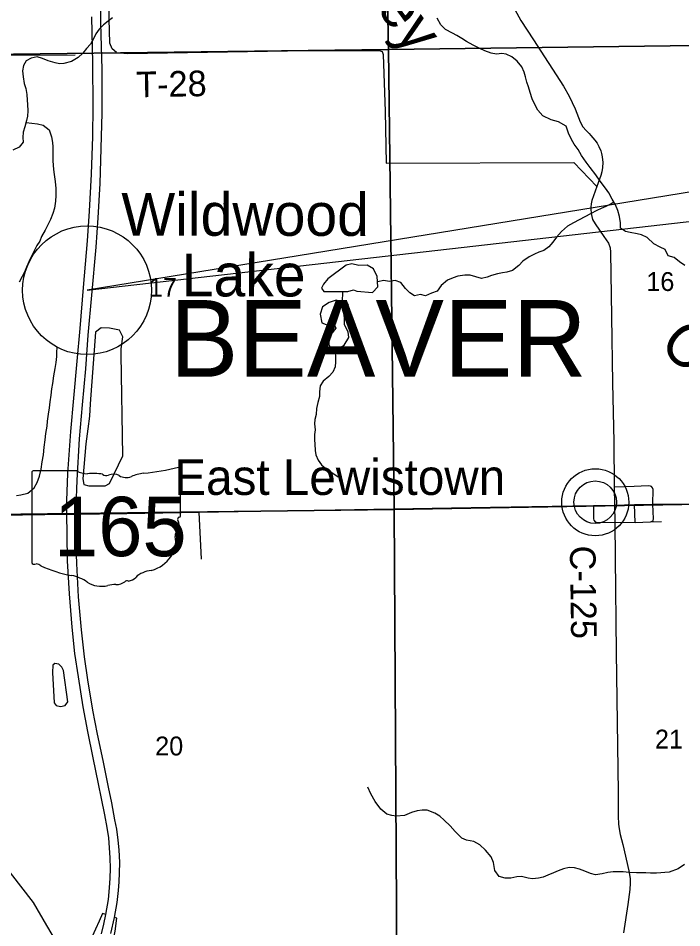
# Model space of a CAD drawing. Extents: x 0 to 36.9, y 0 to 22.
# Drawn here: x 5.386 to 6.858, y 16.582 to 18.601 of the extents above; entities that cross this region are included whole.
import ezdxf

# ---------------------------------------------------------------- set-up
doc = ezdxf.new("R2010")
doc.units = 0
for name, color, linetype in [('GM_X_County_Road', 7, 'Continuous'), ('GM_X_County_Road_Text', 7, 'Continuous'), ('GM_X_Interchange_Ramps', 7, 'Continuous'), ('GM_X_Minor_Lake', 7, 'Continuous'), ('GM_X_Minor_Lake_Text', 7, 'Continuous'), ('GM_X_Minor_River', 7, 'Continuous'), ('GM_X_Minor_River_Text', 7, 'Continuous'), ('GM_X_Section', 7, 'Continuous'), ('GM_X_Section_Text', 7, 'Continuous'), ('GM_X_State_Location', 7, 'Continuous'), ('GM_X_State_Route', 7, 'Continuous'), ('GM_X_State_Shield', 7, 'Continuous'), ('GM_X_Township_Road', 7, 'Continuous'), ('GM_X_Township_Road_Text', 7, 'Continuous'), ('GM_X_Township_Text', 7, 'Continuous'), ('GM_X_Unincorporated', 7, 'Continuous'), ('GM_X_Unincorporated_Location', 7, 'Continuous'), ('GM_X_Unincorporated_Text', 7, 'Continuous'), ('SH_Text', 7, 'Continuous')]:
    doc.layers.add(name, color=color, linetype=linetype)

msp = doc.modelspace()

# ---------------------------------------------------------------- linework, layer by layer
at = {"layer": 'GM_X_County_Road'}
for points in [[(5.6045, 18.5243), (5.5945, 18.533), (5.5895, 18.5452), (5.5877, 18.5992), (5.5866, 18.6737), (5.5863, 18.715), (5.5843, 18.7612), (5.5835, 18.8365), (5.5797, 18.9426), (5.5744, 19.0226), (5.5675, 19.0889), (5.5575, 19.1695), (5.5019, 19.5264)], [(6.3225, 19.0341), (6.3608, 18.9363), (6.4096, 18.8146), (6.4758, 18.6464), (6.4875, 18.6201), (6.5008, 18.5958), (6.5286, 18.5528), (6.5955, 18.45), (6.6081, 18.4277), (6.6215, 18.3998), (6.6322, 18.3709), (6.638, 18.3599), (6.6455, 18.3515), (6.6522, 18.3445)], [(6.6522, 18.3445), (6.6562, 18.3403), (6.6649, 18.3302), (6.67, 18.3232), (6.6739, 18.3157), (6.678, 18.306), (6.6795, 18.3003), (6.6811, 18.2932), (6.6826, 18.2807), (6.6819, 18.2696), (6.6803, 18.2595), (6.678, 18.2515), (6.6692, 18.2272), (6.6617, 18.2064), (6.6586, 18.1962), (6.6571, 18.1886), (6.6562, 18.1816), (6.6558, 18.1758), (6.6565, 18.169)], [(6.6565, 18.169), (6.6567, 18.1671), (6.6582, 18.1604), (6.66, 18.1542), (6.6653, 18.1444), (6.6848, 18.1162), (6.695, 18.1011), (6.699, 18.0909), (6.7, 18.0814), (6.7022, 17.9387), (6.7043, 17.7909), (6.7067, 17.6614), (6.708, 17.5601), (6.7082, 17.5202)], [(6.7082, 17.5202), (6.7089, 17.4821), (6.7097, 17.403), (6.7125, 17.1927), (6.7164, 16.8829), (6.7165, 16.83), (6.7175, 16.8118), (6.7188, 16.8014), (6.7212, 16.7888), (6.7268, 16.7665), (6.7404, 16.7086), (6.7432, 16.6916), (6.7434, 16.6807), (6.7423, 16.6672), (6.7379, 16.634), (6.7285, 16.5707)]]:
    msp.add_lwpolyline(points, dxfattribs=at)
at = {"layer": 'GM_X_Interchange_Ramps'}
for points in [[(5.5806, 16.6115), (5.5732, 16.614), (5.5656, 16.5967), (5.5579, 16.5791), (5.5503, 16.5629), (5.5411, 16.5466), (5.5308, 16.5317), (5.5207, 16.5178), (5.516, 16.5115), (5.5071, 16.5), (5.504, 16.4959)], [(5.5806, 16.3575), (5.584, 16.3603), (5.592, 16.3688), (5.5978, 16.3798), (5.6009, 16.3877), (5.6029, 16.3957), (5.6043, 16.4061), (5.6043, 16.4157), (5.6025, 16.4264), (5.5984, 16.4417), (5.5932, 16.4593), (5.5906, 16.4722), (5.5895, 16.4843), (5.5893, 16.4953), (5.5899, 16.5078), (5.5915, 16.5216), (5.596, 16.5483), (5.6011, 16.5745), (5.605, 16.6036), (5.5996, 16.605)]]:
    msp.add_lwpolyline(points, dxfattribs=at)
at = {"layer": 'GM_X_Minor_Lake'}
for points in [[(6.1721, 17.9919), (6.184, 18.0043), (6.1825, 18.0274), (6.1742, 18.0447), (6.1604, 18.0525), (6.1414, 18.0522), (6.1258, 18.0557), (6.1133, 18.0525), (6.0731, 18.0222), (6.063, 18.0103), (6.059, 18.0015), (6.0637, 17.9939), (6.1169, 17.9941), (6.1294, 17.9981), (6.1374, 17.9948)], [(6.1374, 17.9948), (6.1721, 17.9919)], [(6.1091, 17.956), (6.1189, 17.9652), (6.0913, 17.9746), (6.0758, 17.9698), (6.0608, 17.9601), (6.0557, 17.9441), (6.0595, 17.9248), (6.0732, 17.9197), (6.0869, 17.9206), (6.0908, 17.9124), (6.0822, 17.9023), (6.0744, 17.892), (6.0747, 17.8768), (6.0794, 17.8651), (6.0931, 17.8657), (6.1089, 17.8751), (6.1197, 17.8923), (6.118, 17.9048), (6.114, 17.9112), (6.1101, 17.921)], [(6.1101, 17.921), (6.1091, 17.956)], [(5.6142, 17.8542), (5.6144, 17.8669), (5.6185, 17.8932), (5.6107, 17.9086), (5.5885, 17.9128), (5.5699, 17.9137), (5.5579, 17.9036), (5.5456, 17.745), (5.5446, 17.7173), (5.5408, 17.6891), (5.5361, 17.6564), (5.5293, 17.578), (5.5315, 17.5655), (5.5425, 17.5631), (5.579, 17.5625), (5.5888, 17.568), (5.6186, 17.6294)], [(5.6186, 17.6294), (5.6142, 17.8542)], [(5.4869, 17.1527), (5.4833, 17.1603), (5.4764, 17.167), (5.4676, 17.1683), (5.4627, 17.1645), (5.4626, 17.1485), (5.466, 17.0813), (5.4703, 17.075), (5.4798, 17.0732), (5.4904, 17.0753), (5.496, 17.0837)], [(5.496, 17.0837), (5.4869, 17.1527)]]:
    msp.add_lwpolyline(points, dxfattribs=at)
at = {"layer": 'GM_X_Minor_River'}
for points in [[(5.5956, 18.6016), (5.5855, 18.5942), (5.5754, 18.5857), (5.5657, 18.576), (5.5586, 18.566), (5.5539, 18.5565), (5.5465, 18.543), (5.5379, 18.5334), (5.5294, 18.523), (5.5189, 18.5137), (5.5047, 18.5043), (5.4873, 18.4999), (5.4778, 18.4993), (5.4679, 18.5014), (5.453, 18.5061), (5.44, 18.5112), (5.4285, 18.5148), (5.4149, 18.5119), (5.404, 18.506), (5.3977, 18.4956), (5.3961, 18.4838), (5.3971, 18.4705), (5.3992, 18.4561), (5.4028, 18.4448), (5.4053, 18.4316), (5.4063, 18.4191), (5.4069, 18.4088), (5.4075, 18.3952), (5.407, 18.3834), (5.4049, 18.3739), (5.4009, 18.3594), (5.397, 18.3479), (5.3964, 18.3361), (5.3974, 18.3259), (5.3881, 18.3144), (5.3745, 18.308)], [(6.6767, 18.2387), (6.667, 18.253), (6.6542, 18.2691), (6.6456, 18.2814), (6.6351, 18.296), (6.6276, 18.3092), (6.6194, 18.3208), (6.6135, 18.3317), (6.6065, 18.3453), (6.6012, 18.3611), (6.5844, 18.3707), (6.5683, 18.3749), (6.5496, 18.3841), (6.5383, 18.3968), (6.5309, 18.4103), (6.5257, 18.4216), (6.5213, 18.436), (6.5177, 18.4481), (6.5144, 18.459), (6.5112, 18.4703), (6.508, 18.4809), (6.5028, 18.493), (6.4927, 18.5057), (6.4812, 18.5146), (6.4685, 18.5208), (6.4586, 18.5225), (6.4465, 18.5208), (6.4354, 18.5229), (6.4213, 18.5279), (6.4098, 18.5338), (6.3952, 18.5408), (6.3807, 18.5492), (6.3703, 18.5555), (6.3588, 18.5625), (6.3492, 18.5676), (6.3335, 18.5753), (6.3234, 18.5862), (6.3152, 18.6008)], [(5.4036, 18.3694), (5.4293, 18.366), (5.4419, 18.3631), (5.455, 18.3531), (5.4602, 18.3373), (5.4623, 18.3248), (5.4629, 18.3149), (5.4632, 18.299), (5.463, 18.2842), (5.4636, 18.2747), (5.4645, 18.2649), (5.4659, 18.2535), (5.468, 18.238), (5.4695, 18.2224), (5.4697, 18.2072), (5.4688, 18.1947), (5.4664, 18.1791), (5.4629, 18.1673), (5.4578, 18.1543), (5.4534, 18.1447), (5.446, 18.1305), (5.438, 18.116), (5.434, 18.106), (5.4277, 18.096), (5.4222, 18.0857), (5.4152, 18.0708), (5.4097, 18.06), (5.4046, 18.0478), (5.3999, 18.0374), (5.3947, 18.0275), (5.3885, 18.0152)], [(6.8642, 18.0519), (6.8523, 18.06), (6.8411, 18.0697), (6.8274, 18.0733), (6.8211, 18.0872), (6.8096, 18.0923), (6.7958, 18.1), (6.7811, 18.1142), (6.7685, 18.12), (6.7589, 18.1221), (6.7429, 18.1249), (6.7327, 18.127), (6.7219, 18.1348), (6.7217, 18.1469), (6.7199, 18.1605), (6.7159, 18.1737), (6.7107, 18.1862), (6.7033, 18.1993), (6.6958, 18.2129), (6.6884, 18.2237), (6.6767, 18.2387)], [(6.707, 18.1927), (6.7012, 18.1887), (6.6891, 18.1831), (6.6793, 18.178), (6.6691, 18.1737), (6.6555, 18.1666), (6.6431, 18.16), (6.6175, 18.1466), (6.6043, 18.1388), (6.5912, 18.1272), (6.58, 18.1145), (6.5718, 18.1037), (6.5632, 18.0933), (6.5515, 18.0852), (6.541, 18.0816), (6.5308, 18.0772), (6.5191, 18.0713), (6.5055, 18.0616), (6.4966, 18.0516), (6.4827, 18.0407), (6.4698, 18.0367), (6.4603, 18.0354), (6.4493, 18.0333), (6.4357, 18.0297), (6.4259, 18.0261), (6.4134, 18.0229), (6.4008, 18.0268), (6.3886, 18.0301), (6.3764, 18.0306), (6.3612, 18.0281), (6.3506, 18.0241), (6.3385, 18.019), (6.3243, 18.0077), (6.3154, 17.9951), (6.3025, 17.9907), (6.2893, 17.9847), (6.2786, 17.9876), (6.2649, 17.9847), (6.255, 17.991), (6.2453, 18.0011), (6.2344, 18.0138), (6.2218, 18.0186), (6.2089, 18.0161), (6.1971, 18.0185), (6.1833, 18.0155)], [(6.1051, 17.994), (6.1046, 17.9701)], [(5.3822, 17.5417), (5.3921, 17.543), (5.4076, 17.5467), (5.4218, 17.5583), (5.4284, 17.5699), (5.4335, 17.584), (5.437, 17.6), (5.4397, 17.6164), (5.4421, 17.6316), (5.4441, 17.6483), (5.4457, 17.6647), (5.4477, 17.6788), (5.4501, 17.6955), (5.4514, 17.7066), (5.4534, 17.7222), (5.4558, 17.7363), (5.4574, 17.7496), (5.4595, 17.7637), (5.4611, 17.7781), (5.4628, 17.7903), (5.4655, 17.807), (5.4683, 17.823), (5.4703, 17.8367), (5.4716, 17.8497), (5.4722, 17.8596), (5.4728, 17.8698)], [(6.0885, 17.8655), (6.0896, 17.8508), (6.0901, 17.8379), (6.0888, 17.8273), (6.0837, 17.8154), (6.0751, 17.8054), (6.0623, 17.7953), (6.0556, 17.7849), (6.0543, 17.7712), (6.0541, 17.761), (6.0505, 17.7476), (6.0477, 17.7347), (6.0468, 17.7214), (6.0439, 17.7099), (6.0433, 17.7004), (6.0447, 17.6868), (6.0433, 17.6765), (6.0431, 17.6651), (6.0437, 17.6552), (6.0447, 17.6416), (6.0464, 17.6317), (6.0511, 17.62), (6.0585, 17.6095), (6.0701, 17.5998), (6.082, 17.5924), (6.0954, 17.5828)], [(6.8635, 16.7223), (6.85, 16.7126), (6.83, 16.7054), (6.8019, 16.7033), (6.7883, 16.7035), (6.778, 16.7037), (6.7685, 16.7039), (6.7575, 16.7041), (6.7408, 16.7049), (6.7278, 16.7058), (6.718, 16.706), (6.7058, 16.7062), (6.6937, 16.7044), (6.6812, 16.7015), (6.6664, 16.6998), (6.6554, 16.7026), (6.6428, 16.7073), (6.6309, 16.7117), (6.6195, 16.7149), (6.6081, 16.7154), (6.5956, 16.7125), (6.5839, 16.7085), (6.5733, 16.7038), (6.5605, 16.6986), (6.5503, 16.6946), (6.5401, 16.6922), (6.5265, 16.6908), (6.517, 16.6921), (6.5021, 16.6957), (6.4918, 16.6951), (6.479, 16.6922), (6.4661, 16.692), (6.4531, 16.6959), (6.4434, 16.709), (6.4404, 16.7265), (6.4349, 16.7393), (6.4224, 16.7546), (6.4101, 16.7662), (6.3966, 16.7731), (6.3806, 16.7766), (6.3699, 16.781), (6.3549, 16.7955), (6.344, 16.8079), (6.3309, 16.8209), (6.3212, 16.8295), (6.3104, 16.8365), (6.2932, 16.8427), (6.2822, 16.8432), (6.2709, 16.8415), (6.2584, 16.8379), (6.2426, 16.8315), (6.2244, 16.83), (6.2145, 16.8314), (6.2038, 16.8342), (6.1907, 16.845), (6.1778, 16.8622), (6.1684, 16.8795), (6.1613, 16.8938)]]:
    msp.add_lwpolyline(points, dxfattribs=at)
at = {"layer": 'GM_X_Section'}
for points in [[(7.1591, 19.5574), (7.173, 18.5435), (6.2072, 18.5313), (6.1867, 19.5319)], [(6.1867, 19.5319), (6.2072, 18.5313), (5.197, 18.519), (5.1777, 19.5195)], [(6.2072, 18.5313), (7.173, 18.5435), (7.1983, 17.5272), (6.2201, 17.5106)], [(5.197, 18.519), (6.2072, 18.5313), (6.2201, 17.5106), (5.2141, 17.498)], [(7.1983, 17.5272), (7.2171, 16.5161), (6.226, 16.4996), (6.2201, 17.5106)], [(6.2201, 17.5106), (6.226, 16.4996), (5.2292, 16.4845), (5.2141, 17.498)]]:
    msp.add_lwpolyline(points, close=True, dxfattribs=at)
at = {"layer": 'GM_X_State_Route'}
for points in [[(5.5147, 17.5134), (5.5147, 17.5163), (5.5167, 17.5757), (5.5221, 17.667), (5.5287, 17.7425), (5.5359, 17.8227), (5.5417, 17.8974), (5.5497, 17.9863), (5.559, 18.0927), (5.5636, 18.158), (5.568, 18.2335), (5.5726, 18.3901), (5.5723, 18.4865), (5.5698, 18.5896), (5.5687, 18.6515)], [(5.571, 16.5689), (5.5759, 16.5897), (5.5806, 16.6115), (5.5865, 16.6445), (5.589, 16.6709), (5.5903, 16.692), (5.5908, 16.7139), (5.5902, 16.7369), (5.5887, 16.7596), (5.5869, 16.7816), (5.5836, 16.8043), (5.5781, 16.8328), (5.5711, 16.869), (5.5645, 16.9011), (5.5526, 16.9591), (5.5408, 17.0177), (5.5303, 17.0721), (5.5196, 17.1386), (5.512, 17.1904), (5.5061, 17.249), (5.4997, 17.3228), (5.4959, 17.3965), (5.4946, 17.4549), (5.4944, 17.4998), (5.4944, 17.5107), (5.4943, 17.5306), (5.4962, 17.59), (5.5031, 17.6832), (5.5098, 17.7573), (5.517, 17.8398), (5.5234, 17.9122), (5.5308, 18.003), (5.54, 18.1068), (5.5446, 18.1725), (5.5489, 18.2544), (5.5514, 18.3384), (5.5522, 18.4044), (5.5518, 18.5008), (5.5494, 18.6039)], [(5.504, 16.4959), (5.45, 16.5871), (5.4199, 16.6383), (5.3454, 16.7333), (5.2454, 16.8581), (5.0508, 17.0699), (5.0061, 17.1277), (4.9804, 17.1698), (4.8265, 17.4934), (4.741, 17.6571), (4.6391, 17.8287), (4.4642, 18.1227), (4.4317, 18.177)], [(6.4333, 17.5154), (6.6618, 17.5193), (6.7082, 17.5202), (6.7526, 17.5212), (6.7935, 17.5224), (7.0911, 17.5244)], [(5.5919, 16.5691), (5.5996, 16.605), (5.6055, 16.638), (5.609, 16.665), (5.6104, 16.6836), (5.6111, 16.7038), (5.6113, 16.7272), (5.6098, 16.7552), (5.6081, 16.7761), (5.6047, 16.8012), (5.6006, 16.8215), (5.5937, 16.8595), (5.5864, 16.894), (5.5744, 16.9532), (5.5624, 17.0118), (5.5519, 17.0649), (5.5407, 17.1322), (5.5335, 17.1832), (5.5267, 17.2429), (5.52, 17.3164), (5.5164, 17.3906), (5.5142, 17.4505), (5.5149, 17.4964), (5.5148, 17.5001), (5.5147, 17.5134)], [(5.6272, 17.5017), (5.7874, 17.5041), (6.4333, 17.5154)], [(5.3473, 17.4975), (5.4944, 17.4998), (5.5025, 17.4999), (5.5148, 17.5001), (5.6182, 17.5016), (5.6272, 17.5017)]]:
    msp.add_lwpolyline(points, dxfattribs=at)
at = {"layer": 'GM_X_State_Shield'}
for p, q in [((5.4165, 17.5927), (5.4165, 17.3926)), ((5.5162, 17.5961), (5.4197, 17.5961)), ((5.7461, 17.4964), (5.7461, 17.6011)), ((5.746, 17.4964), (5.7461, 17.4964))]:
    msp.add_line(p, q, dxfattribs=at)
for centre, major_axis, start_param, end_param in [((5.6286, 17.869), (0.3495, 0), 4.814394, 5.042369), ((5.7424, 17.6015), (0.00367, 0), 6.141152, 7.989035), ((5.4202, 17.5931), (0.00382, 0), 1.712693, 3.28349), ((5.5392, 17.6194), (0.037, 0), 4.042523, 4.731795), ((5.5515, 17.4838), (0.133, 0), 1.404758, 1.657858), ((5.5817, 17.5941), (0.0107, 0), 3.836095, 5.185415), ((5.5974, 17.571), (0.0222, 0), 0.950623, 2.079405), ((5.626, 17.6027), (0.0267, 0), 4.081561, 5.145723), ((5.6732, 17.535), (0.0703, 0), 1.699011, 2.107814), ((5.7452, 17.4887), (0.00568, 0), 1.883978, 3.671073), ((5.7091, 17.4755), (0.0341, 0), 5.934695, 6.695948), ((5.7421, 17.496), (0.00393, 0), 5.05454, 6.418171), ((5.7592, 17.4526), (0.0248, 0), 2.387724, 3.262537), ((5.6482, 17.4393), (0.0874, 0), 5.101752, 6.440018), ((5.4203, 17.3921), (0.00385, 0), 3.00124, 4.508301), ((5.4209, 17.4126), (0.0294, 0), 4.665946, 4.897461), ((5.4269, 17.381), (0.0106, 0), 0.519207, 1.627899), ((5.5607, 17.5608), (0.2524, 0), 4.195997, 4.488961), ((5.4855, 17.3027), (0.079, 0), 0.823519, 1.323587), ((5.6851, 17.3364), (0.0479, 0), 1.647645, 2.488434), ((5.5709, 17.38), (0.0501, 0), 4.026481, 4.996735), ((5.5998, 17.3108), (0.0412, 0), 1.495662, 1.94098), ((5.6035, 17.365), (0.0267, 0), 4.691044, 5.507374), ((5.6276, 17.3457), (0.00752, 0), 1.147584, 2.315152), ((5.6244, 17.3732), (0.0282, 0), 4.937069, 5.64225)]:
    msp.add_ellipse(centre, major_axis=major_axis, ratio=0.8, start_param=start_param, end_param=end_param, dxfattribs=at)
at = {"layer": 'GM_X_Township_Road'}
for p, q in [((5.2008, 18.5186), (5.5124, 18.5192)), ((5.7928, 17.4), (5.7874, 17.5041)), ((6.754, 17.4817), (6.7526, 17.5212))]:
    msp.add_line(p, q, dxfattribs=at)
for points in [[(5.6045, 18.5243), (5.6289, 18.5225), (6.0274, 18.5292), (6.1149, 18.5292), (6.1239, 18.5292)], [(6.1239, 18.5292), (6.1817, 18.5292), (6.1886, 18.5286), (6.1932, 18.5268), (6.1956, 18.5204), (6.2, 18.3939), (6.2019, 18.2788), (6.6185, 18.2805), (6.6692, 18.2272)], [(6.7882, 17.4833), (6.7917, 17.4842), (6.7941, 17.4861), (6.795, 17.4893), (6.7935, 17.5224), (6.794, 17.555), (6.7931, 17.5583), (6.7908, 17.5611), (6.788, 17.5623), (6.7833, 17.5626), (6.7525, 17.5613), (6.708, 17.5601)], [(6.6618, 17.5193), (6.6621, 17.4895), (6.6626, 17.4865), (6.6659, 17.4832), (6.6715, 17.4815), (6.7089, 17.4821), (6.754, 17.4817), (6.7882, 17.4833), (6.813, 17.484)]]:
    msp.add_lwpolyline(points, dxfattribs=at)
at = {"layer": 'GM_X_Unincorporated'}
for radius in [0.0744, 0.0472]:
    msp.add_circle((6.6659, 17.5264), radius, dxfattribs=at)
at = {"layer": 'GM_X_Unincorporated_Location'}
msp.add_line((6.6659, 17.5264), (6.6659, 17.5264), dxfattribs=at)
at = {"layer": 'SH_Text'}
msp.add_lwpolyline([(5.5389, 17.9969), (9.1094, 18.4044), (9.1094, 18.5783)], close=True, dxfattribs=at)
msp.add_circle((5.5389, 17.9969), 0.1428, dxfattribs=at)

# ---------------------------------------------------------------- texts
at = {"layer": 'GM_X_County_Road_Text'}
msp.add_text('C-125', height=0.05682, rotation=270.8259, dxfattribs=at).set_placement((6.6095, 17.4297))
at = {"layer": 'GM_X_Minor_Lake_Text'}
for s, rotation, p in [('Wildwood', 359.9582, (5.6148, 18.118)), ('Lake', 359.9579, (5.7489, 17.9833))]:
    msp.add_text(s, height=0.09473, rotation=rotation, dxfattribs=at).set_placement(p)
at = {"layer": 'GM_X_Minor_River_Text'}
for s, height, rotation, p in [('Turkey', 0.09473, 305.8709, (6.0299, 18.8302)), ('Creek', 0.09474, 316.7828, (6.8044, 17.8722))]:
    msp.add_text(s, height=height, rotation=rotation, dxfattribs=at).set_placement(p)
at = {"layer": 'GM_X_Section_Text'}
for s, p in [('16', (6.779, 17.9953)), ('17', (5.6761, 17.9825)), ('21', (6.7982, 16.9798)), ('20', (5.6899, 16.9645))]:
    msp.add_text(s, height=0.04186, rotation=0, dxfattribs=at).set_placement(p)
at = {"layer": 'GM_X_State_Location'}
msp.add_text('165', height=0.000189, rotation=0, dxfattribs=at).set_placement((5.5107, 17.4655))
for s, p in [('s', (5.5776, 17.4793)), ('r', (5.5775, 17.4793))]:
    msp.add_text(s, height=0.000189, dxfattribs=at).set_placement(p)
at = {"layer": 'GM_X_State_Shield'}
msp.add_text('165', height=0.13184, dxfattribs=at).set_placement((5.4656, 17.4067))
at = {"layer": 'GM_X_Township_Road_Text'}
msp.add_text('T-28', height=0.05682, rotation=1.0617, dxfattribs=at).set_placement((5.6484, 18.425))
at = {"layer": 'GM_X_Township_Text'}
msp.add_text('BEAVER', height=0.17045, rotation=0, dxfattribs=at).set_placement((5.7223, 17.8048))
at = {"layer": 'GM_X_Unincorporated_Text'}
msp.add_text('East Lewistown', height=0.078977, rotation=0, dxfattribs=at).set_placement((5.7324, 17.5427))

doc.saveas('drawing.dxf')
